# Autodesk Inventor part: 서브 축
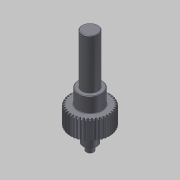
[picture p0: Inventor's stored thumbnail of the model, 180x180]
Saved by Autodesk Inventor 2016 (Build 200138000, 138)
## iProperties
Created: 2016-02
Part Number: 서브 축
Material: 강철, 연강
Document SubType Name: Modeling
Designer: mdu
Categories: <?xml version="1.0" encoding="UTF-16"?> <MemberInstance><Categories><FamilyTemplate><FamilyTemplateParameter ValueType="xs:double" Id="1" ObjectReferenceKey="da
Density: 7.86 g/cm^3
Appearance: 강철
CustomPartVersion: 1
Author: mdu
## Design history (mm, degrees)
sketch "Sketch1"
  geometry: C1 r 21 at (0, 0)
  constraints: 1 centre point
  dimensions: "d0" = 42 diameter of C1 (= da_da)
extrude "Extrusion1" new body sketch "Sketch1" distance "d1" = 20 (= da_b); taper "d2" = 0 deg
workplane "Work Plane2"
feature "피치 지름" dims "d4" = 10, "d5" = 0
workplane "Work Plane8"
workplane "Work Plane9"
chamfer "모따기1" distance "d49" = 1; stored, may be unused: second distance "d50" = 2, angle "d51" = 45 deg
sketch "스케치3"
  geometry: C1 r 12.5 at (0, 0); 1 further point
  constraints: 1 centre point, 1 coincident
  dimensions: "d52" = 25 diameter of C1
extrude "돌출2" join sketch "스케치3" distance "d53" = 16; taper "d54" = 0 deg
sketch "스케치4"
  geometry: C1 r 8.5 at (0, 0); 1 further point
  constraints: 1 centre point, 1 coincident
  dimensions: "d55" = 17 diameter of C1
extrude "돌출3" join sketch "스케치4" distance "d56" = 53; taper "d57" = 0 deg
sketch "스케치5"
  geometry: C1 r 7.5 at (0, 0); 1 further point
  constraints: 1 centre point, 1 coincident
  dimensions: "d62" = 15 diameter of C1
extrude "돌출4" join sketch "스케치5" distance "d63" = 16; taper "d64" = 0 deg
sketch "스케치6"
  geometry: C1 r 4 at (0, 0); 1 further point
  constraints: 1 centre point, 1 coincident
  dimensions: "d65" = 8 diameter of C1
extrude "돌출5" join sketch "스케치6" distance "d66" = 7; taper "d67" = 0 deg
chamfer "모따기2" distance "d58" = 0.5; stored, may be unused: second distance "d59" = 2, angle "d60" = 45 deg
fillet "모깎기1" dims "d61" = 0.5
feature "스퍼 기어" dims "d34" = 4.5 deg (computed from da_z), "da_b" = 20, "da_d" = 40, "da_aw" = 31, "da_da" = 42, "da_df" = 37.5, "da_dw" = 40, angle "da_beta" = 0 deg, "da_lefttooth" = 0, "da_righttooth" = 0
body "Solid1"
sketch "Sketch2"
  geometry: C1 r 21 at (0, 0) reference; C2 r 20 at (0, 0)
  constraints: 1 centre point, 1 coincident
  dimensions: "d3" = 40 diameter of C2 (= da_dw)
body "Srf1"
other parameters: "d16" = 31 (= da_aw), "d17" = 0, "d39" = 0, "d41" = 0, "d43" = 31 (= da_aw), "d46" = 31 (= da_aw), "d47" = 0, "d48" = 0
